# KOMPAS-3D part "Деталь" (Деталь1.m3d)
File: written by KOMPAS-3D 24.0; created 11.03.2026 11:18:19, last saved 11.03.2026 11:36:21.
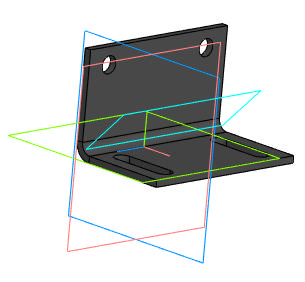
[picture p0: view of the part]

Document properties: Автор: R2D2; Полное имя файла: E:\Работа\Зайцев\БКВ APL-210N Блок концевых выключателей DN.ru\исходные материалы\Деталь1.m3d

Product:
- Part/product: Деталь
    Масса: 0.040625

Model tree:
1. Эскиз:1
2. Листовое тело:1
     Расстояние 1 = 50; Радиус сгиба = 3; Коэффициент = 0.4; Величина сгиба = 10
3. Эскиз:2  (with: Грань.Листовое тело:1)
4. Вырез в листовом теле:1
     Глубина выреза = 10
5. Средняя плоскость:1  (with: Грань.Листовое тело:1)
6. Эскиз:3  (with: Грань.Листовое тело:1)
7. Элемент выдавливания:1
     Расстояние 2 = 10
8. Зеркальный массив:2
9. Экземпляр ( 1 )
10. Экземпляр ( 2 )  (with: Элемент выдавливания:1)

Expressions: v76/2; 35.4/2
